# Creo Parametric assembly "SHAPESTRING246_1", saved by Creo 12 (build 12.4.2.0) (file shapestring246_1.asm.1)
Units: Custom; MM, KILOGRAM, SECS

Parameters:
  PTC_WM_ITERATION = "0"
  PTC_WM_VERSION = "-.0"
  PTC_WM_LIFECYCLE_STATE = "In Work"
  PTC_WM_LIFECYCLE = "MO_CADDocument"
  PTC_WM_CREATED_BY = "Maximilian Roepper (Z0017RMS: MO)"
  PTC_WM_CREATED_ON = "18-Sep-26 11:36:42 AM"
  PTC_WM_MODIFIED_BY = "Maximilian Roepper (Z0017RMS: MO)"
  PTC_WM_MODIFIED_ON = "18-Sep-26 11:36:46 AM"
  PDMLINKNUMBER = "PDM000071454875"
  PTC_WM_NAME = "shapestring246_1.asm"
  PTC_WM_NUMBER = "PDM000071454875"

Other parameters: WEIGHT, WEIGHT_FACTOR, WEIGHT_ADD, MC_ERRORS, SUPPLIER, ISPOSITIONINGASSEMBLY

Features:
  1. coordinate system
  2. imported feature
  3. component "SHAPESTRING098_1"
  4. component "SHAPESTRING245_1"

Other named items: DRW_VIEW_ORG, ROUGH-GROB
